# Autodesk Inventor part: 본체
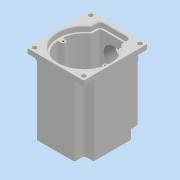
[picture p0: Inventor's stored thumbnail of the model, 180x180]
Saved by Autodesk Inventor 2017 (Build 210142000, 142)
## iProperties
Part Number: 본체
Material: 일반
Document SubType Name: Modeling
Designer: MRC
Density: 1 g/cm^3
Appearance: 기본값
Author: MRC
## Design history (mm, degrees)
sketch "스케치4"
  geometry: L1 (49, -55)-(-49, -55); L2 (-49, -55)-(-49, 55); L3 (-49, 55)-(49, 55); L4 (49, 55)-(49, -55); L5 (49, -55)-(-49, 55); L6 (-49, -55)-(49, 55); 1 further point
  constraints: 12 end point, 2 midpoint, 2 parallel, 1 horizontal, 1 perpendicular
  dimensions: "d6" = 98 distance of L2.end L3.end; "d7" = 110 distance of L1.end L2.end
extrude "돌출2" new body sketch "스케치4" distance "d8" = 130; taper "d9" = 0 deg
node "작업 평면1"
sketch "스케치6"
  geometry: L1 (-33, 28)-(-49, 28); L2 (-49, 28)-(-49, 55); L3 (-49, 55)-(-33, 55); L4 (-33, 55)-(-33, 28); L5 (-49, 55)-(49, 55) reference; L6 (-49, -55)-(-49, 55) reference; 1 further point
  constraints: 8 end point, 2 parallel, 1 horizontal, 1 perpendicular
  dimensions: "d11" = 16 distance of L2.end L3.end; "d12" = 27 distance of L2.end L1.end
extrude "돌출3" cut sketch "스케치6" stored distance "d13" = 10; taper "d14" = 0 deg
sketch "스케치12"
  geometry: L1 (-49, -55)-(49, -55) reference; L2 (-49, 55)-(-49, -55) reference; L3 (49, -55)-(49, 55) reference; L4 (49, 55)-(-49, 55) reference; L5 (-23, 30.143)-(-23, 45); L6 (-23, 45)-(23, 45); L7 (23, 45)-(23, 30.143); L8 (26, 48)-(-26, 48); L9 (-26, 48)-(-26, 31.729); L10 (26, 31.729)-(26, 48); A1 r 42 centre (0, -5) between (-23, 30.143) and (23, 30.143); A2 r 45 centre (0, -5) between (-26, 31.729) and (26, 31.729); 3 further points
  constraints: 12 end point, 4 point on circle, 2 centre point, 2 coincident, 2 parallel, 2 vertical alignment, 1 midpoint, 3 other
  dimensions: "d20" = 84 diameter of A1; "d21" = 50 distance from line of L1 A1.centre; "d23" = 46 distance of L5.end L6.end; "d25" = 23 horizontal distance of point (0, 0) L5.start; "d26" = 50 distance from line of A1.centre L6; "d27" = 23 horizontal distance of point (0, 0) L7.end; "d28" = 3 distance between parallel lines of L6 L8
extrude "돌출5" cut sketch "스케치12" distance "d29" = 121; taper "d30" = 0 deg
extrude "돌출6" cut sketch "스케치12" distance "d31" = 9; taper "d32" = 0 deg
node "작업 평면2"
sketch "스케치16"
  geometry: L1 (-33, -55)-(-49, -55); L2 (-49, -55)-(-49, -38); L3 (-49, -38)-(-33, -38); L4 (-33, -38)-(-33, -55); 2 further points
  constraints: 8 end point, 2 parallel, 1 coincident, 1 horizontal, 1 perpendicular
  dimensions: "d34" = 17 distance of L1.end L2.end; "d35" = 16 distance of L2.end L3.end
extrude "돌출7" cut sketch "스케치16" stored distance "d36" = 3; taper "d37" = 0 deg
fillet "모깎기1" dims "d38" = 6
fillet "모깎기2" dims "d39" = 3
fillet "모깎기3" dims "d40" = 3
fillet "모깎기4" dims "d41" = 3
fillet "모깎기5" dims "d42" = 6
sketch "스케치20"
  geometry: L1 (-49, 28)-(-33, 28) reference; L2 (-49, -38)-(-49, 28) reference; L3 (-33, -38)-(-49, -38) reference; L4 (33, -55)-(-33, -55) reference; L5 (33, -38)-(33, -55) reference; L6 (49, -38)-(33, -38) reference; L7 (49, 28)-(49, -38) reference; L8 (33, 28)-(49, 28) reference; L9 (-33, 55)-(33, 55) reference; L10 (-33, 28)-(-33, 55) reference; L11 (33, 55)-(33, 28) reference; L12 (-49, -5)-(49, -5); A1 r 15 centre (0, -25) between (-8.978, -12.984) and (8.978, -12.984); A2 r 21 centre (0, 6) between (8.978, -12.984) and (-8.978, -12.984); 1 further point
  constraints: 4 point on circle, 2 centre point, 2 end point, 2 midpoint, 2 vertical alignment, 1 horizontal
  dimensions: "d44" = 30 diameter of A1; "d46" = 42 diameter of A2; "d47" = 50 distance between parallel lines of L4 L12; "d48" = 20 distance from line of L12 A1.centre; "d49" = 11 distance from line of A2.centre L12
extrude "돌출8" join sketch "스케치20" distance "d50" = 7; taper "d51" = 0 deg
sketch "스케치23"
  geometry: L1 (27, -21)-(-27, -21); L2 (-27, -21)-(-27, 33); L3 (-27, 33)-(27, 33); L4 (27, 33)-(27, -21); L5 (33, 55)-(-33, 55) reference; L6 (-33, -55)-(33, -55) reference; 3 further points
  constraints: 8 end point, 2 midpoint, 2 parallel, 1 horizontal, 1 perpendicular, 1 vertical alignment
  dimensions: "d53" = 54 distance of L2.end L3.end; "d54" = 54 distance of L1.end L2.end; "d55" = 88 distance between parallel lines of L3 L6
extrude "돌출9" join sketch "스케치23" distance "d56" = 7; taper "d57" = 0 deg
sketch "스케치25"
  geometry: C1 r 11 at (0, -25); A1 r 15 centre (0, -25) between (-8.978, -12.984) and (8.978, -12.984) reference; 1 further point
  constraints: 1 centre point, 1 coincident
  dimensions: "d66" = 22 diameter of C1
extrude "돌출11" cut sketch "스케치25" distance "d67" = 7; taper "d68" = 0 deg
sketch "스케치26"
  geometry: C1 r 11 at (0, 0) reference; C2 r 9.5 at (0, 0); 1 further point
  constraints: 1 centre point, 1 coincident
  dimensions: "d70" = 19 diameter of C2
extrude "돌출12" cut sketch "스케치26" distance "d71" = 3; taper "d72" = 0 deg
sketch "스케치27"
  geometry: C1 r 17.5 at (0, 6); A1 r 21 centre (0, 6) between (8.978, -12.984) and (-8.978, -12.984) reference; 1 further point
  constraints: 1 centre point, 1 coincident
  dimensions: "d73" = 35 diameter of C1
extrude "돌출13" cut sketch "스케치27" distance "d74" = 10; taper "d75" = 0 deg
sketch "스케치28"
  geometry: C1 r 17.5 at (0, 0) reference; C2 r 14 at (0, 0); 1 further point
  constraints: 1 centre point, 1 coincident
  dimensions: "d76" = 28 diameter of C2
extrude "돌출14" cut sketch "스케치28" stored distance "d77" = 10; taper "d78" = 0 deg
sketch "스케치29"
  geometry: C1 r 14 at (0, 6) reference; C2 r 16 at (0, 6); 1 further point
  constraints: 1 centre point, 1 coincident
  dimensions: "d79" = 32 diameter of C2
extrude "돌출15" cut sketch "스케치29" distance "d80" = 8.3; taper "d81" = 0 deg
sketch "스케치30"
  geometry: L1 (98, 0)-(0, 0) reference; C1 r 15 at (49, 89); 2 further points
  constraints: 1 centre point, 1 midpoint, 1 vertical alignment
  dimensions: "d82" = 30 diameter of C1; "d83" = 89 distance from line of C1.centre L1
extrude "돌출16" join sketch "스케치30" distance "d84" = 5; taper "d85" = 0 deg
sketch "스케치31"
  geometry: L1 (16, 130)-(82, 130) reference; L2 (98, 0)-(0, 0) reference; C1 r 22.5 at (49, 40); 2 further points
  constraints: 1 centre point, 1 midpoint, 1 vertical alignment
  dimensions: "d86" = 45 diameter of C1; "d87" = 40 distance from line of L2 C1.centre
extrude "돌출17" join sketch "스케치31" distance "d88" = 10; taper "d89" = 0 deg
sketch "스케치32"
  geometry: C1 r 15 at (0, 0) reference; C2 r 10 at (0, 0); 1 further point
  constraints: 1 centre point, 1 coincident
  dimensions: "d90" = 20 diameter of C2
extrude "돌출18" cut sketch "스케치32" stored distance "d91" = 10; taper "d92" = 0 deg
sketch "스케치33"
  geometry: C1 r 10 at (20, -80) reference; C2 r 15 at (20, -80); 1 further point
  constraints: 1 centre point, 1 coincident
  dimensions: "d93" = 30 diameter of C2
extrude "돌출19" cut sketch "스케치33" distance "d94" = 5; taper "d95" = 0 deg
hole "구멍1" diameter "d98" = 33.376; stored, may be unused: countersink angle "d102" = 90 deg, drill point angle "d104" = 118 deg; dims "d96" = 10, "d97" = 10, "d99" = 70, "d100" = 4, "d101" = 2, "d103" = 77.3
sketch "스케치35"
  geometry: L1 (-49, -55)-(49, -55) reference; L2 (-36, -5)-(36, -5); L3 (-35.777, -1)-(-41.809, -1); L4 (-35.777, -9)-(-41.809, -9); L5 (35.777, -1)-(41.809, -1); L6 (35.777, -9)-(41.809, -9); A1 r 36 centre (0, -5) between (-36, -5) and (36, -5); A2 r 4 centre (-36, -5) between (-36, -9) and (-36, -1); A3 r 4 centre (36, -5) between (36, -1) and (36, -9); A4 r 42 centre (0, -5) between (-25.375, 28.468) and (25.375, 28.468) reference; 1 further point
  constraints: 14 point on circle, 10 end point, 5 horizontal, 4 point on line, 4 tangent, 3 centre point, 2 coincident, 1 vertical alignment
  dimensions: "d105" = 72 diameter of A1; "d106" = 50 distance from line of L1 A1.centre; "d108" = 50 distance between parallel lines of L1 L2; "d109" = 8 diameter of A2; "d110" = 8 diameter of A3
extrude "돌출20" join sketch "스케치35" stored distance "d111" = 105; taper "d112" = 0 deg
sketch "스케치36"
  geometry: A1 r 4 centre (-36, -5) between (-36, -9) and (-36, -1) reference; A2 r 4 centre (36, -5) between (36, -1) and (36, -9) reference; 3 further points
  constraints: 2 coincident
hole "구멍2" sketch "스케치36" at (36, -5), (-36, -5) diameter "d113" = 3.242; stored, may be unused: countersink angle "d117" = 90 deg, drill point angle "d119" = 118 deg; dims "d114" = 7, "d115" = 4, "d116" = 2, "d118" = 9
fillet "모깎기6" dims "d120" = 3
fillet "모깎기7" dims "d121" = 0.3
chamfer "모따기1" distance "d122" = 1; stored, may be unused: second distance "d123" = 2, angle "d124" = 45 deg
chamfer "모따기3" distance "d128" = 1; stored, may be unused: second distance "d129" = 2, angle "d130" = 45 deg
fillet "모깎기8" dims "d131" = 3
fillet "모깎기9" dims "d132" = 3
fillet "모깎기10" dims "d133" = 3
fillet "모깎기11" dims "d134" = 3
fillet "모깎기12" dims "d135" = 3
fillet "모깎기13" dims "d136" = 3
fillet "모깎기14" dims "d137" = 3
fillet "모깎기15" dims "d138" = 3
fillet "모깎기16" dims "d139" = 3
chamfer "모따기4" distance "d140" = 1; stored, may be unused: second distance "d141" = 2, angle "d142" = 45 deg
sketch "스케치38"
  geometry: C1 r 3.5 at (-42, 48); 1 further point
  constraints: 1 centre point
  dimensions: "d143" = 7 diameter of C1; "d144" = 42 horizontal distance of point (0, 0) C1.centre; "d145" = 48 vertical distance of point (0, 0) C1.centre
extrude "돌출21" cut sketch "스케치38" stored distance "d146" = 105; taper "d147" = 0 deg
fillet "모깎기17" dims "d148" = 3
fillet "모깎기18" dims "d149" = 3
fillet "모깎기19" dims "d150" = 0.3
fillet "모깎기20" dims "d151" = 0.3
sketch "스케치43"
  geometry: L1 (-130, 104)-(-130, 83) reference; L2 (-13, 107)-(-127, 107) reference; 2 further points
  constraints: 1 other
  dimensions: "d152" = 65 distance from line of point (-65, 47) L1; "d153" = 60 distance from line of point (-65, 47) L2
feature "엠보싱1" sketch "스케치43" dims "d154" = 0.5, "d155" = 0
chamfer "모따기5" distance "d156" = 0.8; stored, may be unused: second distance "d157" = 2, angle "d158" = 30 deg
node "솔리드2"
mirror "미러1"
mirror "미러3"
mirror "미러4"
mirror "미러5"
